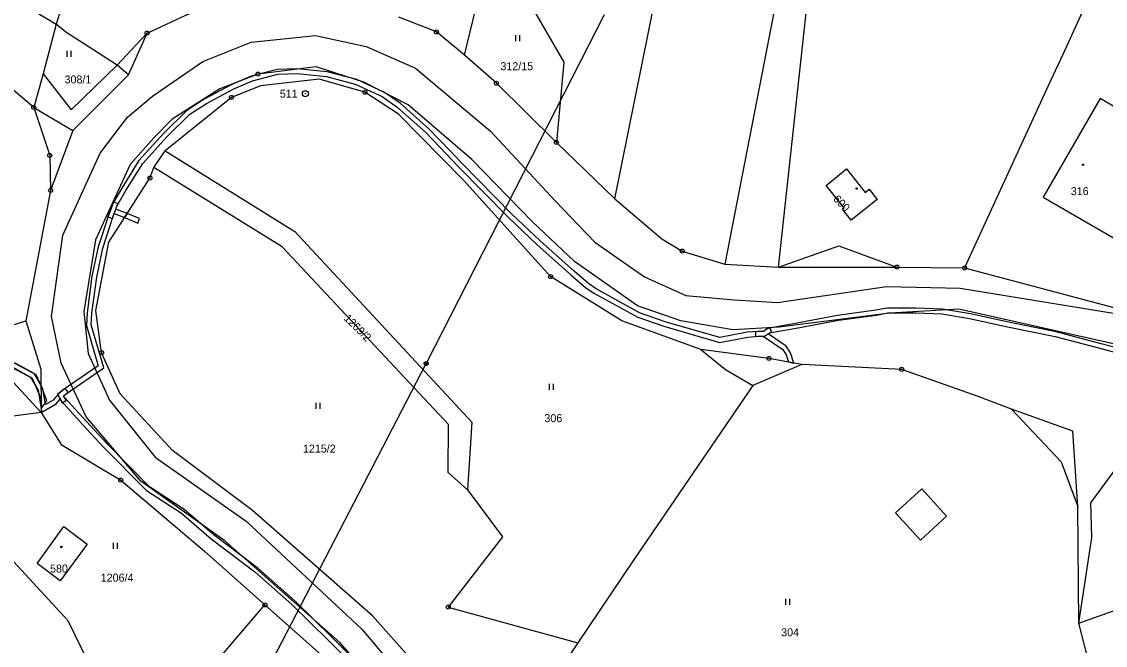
# Model space of a CAD drawing. Extents: x -745926 to -742978, y -968282 to -965689.
# Drawn here: x -745276.5 to -745141.1, y -967249.8 to -967171.8 of the extents above; entities that cross this region are included whole.
import ezdxf

# ---------------------------------------------------------------- set-up
doc = ezdxf.new("R2010")
doc.units = 0
for name, color, linetype in [('Hranice parcel', 7, 'Continuous'), ('Parcelní čísla', 7, 'Continuous'), ('Poz předměty', 7, 'Continuous'), ('Vnitřní kresba', 7, 'Continuous'), ('Věcná břemena k části', 7, 'Continuous'), ('Značky bodu BP', 7, 'Continuous'), ('Značky budov', 7, 'Continuous'), ('Značky kultur', 7, 'Continuous')]:
    doc.layers.add(name, color=color, linetype=linetype)

msp = doc.modelspace()

# ---------------------------------------------------------------- linework, layer by layer
at = {"layer": 'Hranice parcel'}
for p, q in [((-745202.34, -967193.92), (-745183.65, -967100.66)), ((-745221.16, -967175.97), (-745217.61, -967161.45)), ((-745275.54, -967170.09), (-745272.2, -967172.1)), ((-745270.1, -967185.4), (-745263.16, -967178.41)), ((-745275, -967182.5), (-745270.1, -967185.4)), ((-745209.67, -967186.88), (-745202.34, -967193.92)), ((-745259.97, -967189.99), (-745258.56, -967187.92)), ((-745274.07, -967220.66), (-745278.53, -967215.81)), ((-745223.18, -967244.98), (-745207, -967249.46)), ((-745144.35, -967246.97), (-745139.43, -967245.24)), ((-745141.85, -967256.86), (-745144.35, -967246.97)), ((-745207, -967249.46), (-745216.49, -967263.75))]:
    msp.add_line(p, q, dxfattribs=at)
for points in [[(-745168.16, -967104.13), (-745173.28, -967123.27), (-745188.63, -967202.08)], [(-745217.61, -967161.45), (-745208.73, -967176.85), (-745209.67, -967186.88)], [(-745275, -967182.5), (-745281.4, -967177.1), (-745298.48, -967162.66)], [(-745140.8, -967163.7), (-745146.38, -967175.86), (-745148.19, -967179.8), (-745158.64, -967202.56)], [(-745263.16, -967178.41), (-745260.83, -967173.2), (-745253.64, -967169.89), (-745250.27, -967169.74)], [(-745221.16, -967175.97), (-745224.66, -967173.06), (-745229.35, -967171.2)], [(-745272.2, -967172.1), (-745273.8, -967178.3), (-745275, -967182.5)], [(-745263.16, -967178.41), (-745264.55, -967177.2), (-745271, -967173.1), (-745272.2, -967172.1)], [(-745209.67, -967186.88), (-745217.17, -967179.47), (-745221.16, -967175.97)], [(-745178.97, -967214.64), (-745183.09, -967213.89), (-745191.6, -967212.75), (-745201.47, -967209.19), (-745210.38, -967203.66), (-745221.27, -967191.59), (-745229.41, -967183.34), (-745233.59, -967180.6), (-745239.31, -967178.98), (-745246.66, -967179.79), (-745250.28, -967181.24), (-745258.56, -967187.92)], [(-745136.34, -967182.81), (-745137.14, -967184.06), (-745141.69, -967181.37), (-745148.83, -967193.7), (-745135.5, -967201.42), (-745132.62, -967196.44), (-745133.07, -967196.18), (-745128.13, -967187.52)], [(-745329.38, -967185.24), (-745316.28, -967189.84), (-745298.54, -967197.66), (-745281.52, -967209.17), (-745278.48, -967209.96), (-745275.99, -967209.2)], [(-745270.1, -967185.4), (-745272.88, -967192.88), (-745273.88, -967198.16), (-745275.99, -967209.2)], [(-745258.56, -967187.92), (-745242.37, -967198.01), (-745220.24, -967221.85), (-745220.77, -967230.31)], [(-745216.49, -967263.75), (-745227.93, -967251.37), (-745232.64, -967246.06), (-745247.64, -967232.92), (-745257.66, -967225.39), (-745264.18, -967218.33), (-745266.51, -967213.17), (-745267.21, -967207.88), (-745265.62, -967199.33), (-745260.46, -967191.33), (-745259.97, -967189.99)], [(-745220.77, -967230.31), (-745223.2, -967228.15), (-745223.14, -967222.15), (-745243.93, -967199.91), (-745259.97, -967189.99)], [(-745169.56, -967194.02), (-745172.83, -967196.6), (-745173.9, -967195.22), (-745173.7, -967195.06), (-745175.96, -967192.25), (-745173.39, -967190.18), (-745171.07, -967193.15), (-745170.58, -967192.72), (-745169.56, -967194.02)], [(-745202.34, -967193.92), (-745196.49, -967198.94), (-745193.94, -967200.46), (-745188.63, -967202.08)], [(-745188.63, -967202.08), (-745181.92, -967202.47), (-745174.34, -967199.79), (-745167.09, -967202.46), (-745158.64, -967202.56)], [(-745158.64, -967202.56), (-745132.78, -967209.42), (-745128.69, -967209.96), (-745124.38, -967209.63), (-745120.27, -967208.73), (-745116.54, -967206.77), (-745113.27, -967203.97), (-745111.01, -967201.48)], [(-745275.99, -967209.2), (-745274.09, -967215.21), (-745274.07, -967220.66)], [(-745178.97, -967214.64), (-745185.11, -967217.25), (-745200.01, -967239.09), (-745207, -967249.46)], [(-745144.35, -967246.97), (-745144.47, -967232.42), (-745145.11, -967222.97), (-745152.79, -967220.23), (-745156.94, -967218.65), (-745166.5, -967215.25), (-745178.97, -967214.64)], [(-745274.07, -967220.66), (-745271.56, -967224.66), (-745264.12, -967229.1), (-745253.65, -967237.99), (-745246.09, -967244.71)], [(-745292.54, -967223.04), (-745270.72, -967246.67), (-745265.83, -967256.76)], [(-745220.77, -967230.31), (-745216.42, -967236.2), (-745223.18, -967244.98)], [(-745271.23, -967234.9), (-745268.3, -967237.1), (-745271.7, -967241.71), (-745274.57, -967239.54), (-745271.23, -967234.9)], [(-745261.92, -967263.24), (-745260.97, -967262.13), (-745246.09, -967244.71)], [(-745246.09, -967244.71), (-745234.23, -967255.25), (-745221.54, -967274.51)]]:
    msp.add_lwpolyline(points, dxfattribs=at)
at = {"layer": 'Poz předměty'}
for p in [(-745203.68, -967170.92), (-745248.43, -967257.95)]:
    msp.add_line(p, (-745225.94, -967214.52), dxfattribs=at)
for radius in [0.25, 0.2, 0.15, 0.1, 0.05]:
    msp.add_circle((-745225.94, -967214.52), radius, dxfattribs=at)
at = {"layer": 'Vnitřní kresba'}
for p, q in [((-745181.92, -967202.47), (-745173.28, -967123.27)), ((-745266.1, -967152.9), (-745272.2, -967172.1)), ((-745261.55, -967174), (-745260.83, -967173.2)), ((-745247.83, -967174.35), (-745239.76, -967173.5)), ((-745239.76, -967173.5), (-745233.44, -967174.87)), ((-745264.55, -967177.2), (-745261.55, -967174)), ((-745253.84, -967176.77), (-745247.83, -967174.35)), ((-745233.44, -967174.87), (-745227.28, -967177.58)), ((-745270.3, -967182.8), (-745264.55, -967177.2)), ((-745260.13, -967181.09), (-745253.84, -967176.77)), ((-745239.69, -967177.43), (-745246.97, -967178.33)), ((-745233.72, -967179.33), (-745239.69, -967177.43)), ((-745227.28, -967177.58), (-745217.92, -967185.47)), ((-745273.8, -967178.3), (-745270.3, -967182.8)), ((-745246.97, -967178.33), (-745251.73, -967180.19)), ((-745228.21, -967182.17), (-745233.72, -967179.33)), ((-745251.73, -967180.19), (-745257.67, -967183.97)), ((-745263.26, -967183.7), (-745260.13, -967181.09)), ((-745275, -967182.5), (-745273, -967188.5)), ((-745220.23, -967189.01), (-745228.21, -967182.17)), ((-745266.68, -967188.2), (-745263.26, -967183.7)), ((-745257.67, -967183.97), (-745259.98, -967186.31)), ((-745217.92, -967185.47), (-745209.81, -967194.16)), ((-745259.98, -967186.31), (-745262.92, -967189.65)), ((-745273, -967188.5), (-745272.88, -967192.88)), ((-745271.34, -967198.48), (-745266.68, -967188.2)), ((-745262.92, -967189.65), (-745267.29, -967199.06)), ((-745212.7, -967196.78), (-745220.23, -967189.01)), ((-745209.81, -967194.16), (-745204.85, -967199.36)), ((-745207.41, -967201.77), (-745212.7, -967196.78)), ((-745272.79, -967208.64), (-745271.34, -967198.48)), ((-745267.29, -967199.06), (-745268.74, -967208.02)), ((-745204.85, -967199.36), (-745198.64, -967203.69)), ((-745199.51, -967207.32), (-745207.41, -967201.77)), ((-745198.64, -967203.69), (-745193.49, -967206.02)), ((-745181.92, -967202.47), (-745167.09, -967202.46)), ((-745182.01, -967206.91), (-745168.41, -967204.9)), ((-745168.41, -967204.9), (-745159.2, -967205.09)), ((-745159.2, -967205.09), (-745132.78, -967209.42)), ((-745193.49, -967206.02), (-745187.43, -967206.57)), ((-745194.1, -967209.19), (-745199.51, -967207.32)), ((-745187.43, -967206.57), (-745182.01, -967206.91)), ((-745159.37, -967207.72), (-745167.98, -967208.21)), ((-745133.6, -967213.53), (-745159.37, -967207.72)), ((-745271.56, -967214.49), (-745272.79, -967208.64)), ((-745268.74, -967208.02), (-745268.19, -967213.26)), ((-745167.98, -967208.21), (-745181.8, -967209.97)), ((-745187.59, -967210.32), (-745194.1, -967209.19)), ((-745181.8, -967209.97), (-745187.59, -967210.32)), ((-745191.6, -967212.75), (-745188.51, -967215.27)), ((-745268.45, -967221.18), (-745271.56, -967214.49)), ((-745268.19, -967213.26), (-745265.52, -967219.12)), ((-745188.51, -967215.27), (-745185.11, -967217.25)), ((-745265.52, -967219.12), (-745259.8, -967226.22)), ((-745274.07, -967220.66), (-745292.54, -967223.04)), ((-745261.59, -967229.23), (-745268.45, -967221.18)), ((-745152.79, -967220.23), (-745146.59, -967226.8)), ((-745259.8, -967226.22), (-745248.44, -967234.23)), ((-745142.87, -967231.93), (-745138.92, -967226.57)), ((-745146.59, -967226.8), (-745144.47, -967232.42)), ((-745251.09, -967236.71), (-745261.59, -967229.23)), ((-745167.28, -967233.19), (-745164, -967230.19)), ((-745164, -967230.19), (-745160.9, -967233.6)), ((-745142.75, -967236.26), (-745142.87, -967231.93)), ((-745164.17, -967236.59), (-745167.28, -967233.19)), ((-745248.44, -967234.23), (-745233.99, -967247.73)), ((-745160.9, -967233.6), (-745164.17, -967236.59)), ((-745236.74, -967249.4), (-745251.09, -967236.71)), ((-745144.35, -967246.97), (-745142.75, -967236.26)), ((-745233.99, -967247.73), (-745229.89, -967252.56)), ((-745232.33, -967254.41), (-745236.74, -967249.4))]:
    msp.add_line(p, q, dxfattribs=at)
at = {"layer": 'Věcná břemena k části'}
for points in [[(-745137.88, -967213.02), (-745141.75, -967212), (-745147.19, -967210.55), (-745153.16, -967209.34), (-745157.92, -967208.3), (-745161.42, -967207.72), (-745164.73, -967207.6), (-745168.3, -967207.6), (-745169.75, -967207.87), (-745174.51, -967208.5), (-745179.34, -967209.43), (-745183.24, -967210.13), (-745183.83, -967210.5), (-745184.49, -967210.52), (-745185.82, -967210.61), (-745189.24, -967211.28), (-745196.06, -967209.29), (-745199.26, -967208.17), (-745204.68, -967205.2), (-745205.65, -967204.53), (-745207.45, -967202.99), (-745211.7, -967199.19), (-745215.24, -967195.84), (-745221.54, -967189.43), (-745222.9, -967187.96), (-745225.62, -967185.16), (-745229.17, -967181.97), (-745231.16, -967180.62), (-745234.62, -967179.01), (-745238.3, -967178.04), (-745242.06, -967177.66), (-745244.55, -967177.76), (-745247.83, -967178.61), (-745250.25, -967179.64), (-745253.68, -967181.47), (-745255.86, -967182.88), (-745258.75, -967185.72), (-745261.84, -967189.15), (-745264, -967192.6), (-745265.16, -967194.6), (-745265.37, -967195.28), (-745265.61, -967195.9), (-745266.95, -967199.95), (-745267.71, -967203.61)], [(-745233.98, -967252.49), (-745237.73, -967248.75), (-745242.32, -967244.23), (-745246.97, -967240.11), (-745252.43, -967236), (-745256.17, -967232.77), (-745260.52, -967229.92), (-745265.87, -967224.52), (-745268.41, -967221.77), (-745271.1, -967218.83), (-745271.26, -967218.55), (-745270.94, -967218.3), (-745266.25, -967215.07), (-745267.8, -967209.7), (-745267.71, -967208.24), (-745267.11, -967203.71), (-745266.37, -967200.11), (-745265.05, -967196.1), (-745264.81, -967195.48), (-745264.6, -967194.84), (-745263.48, -967192.9), (-745261.36, -967189.51), (-745258.31, -967186.14), (-745255.48, -967183.36), (-745253.38, -967181.99), (-745249.99, -967180.18), (-745247.63, -967179.17), (-745244.47, -967178.36), (-745242.08, -967178.26), (-745238.4, -967178.64), (-745234.82, -967179.57), (-745231.46, -967181.14), (-745229.55, -967182.45), (-745226.04, -967185.6), (-745223.34, -967188.38), (-745221.98, -967189.85), (-745215.66, -967196.26), (-745212.1, -967199.63), (-745207.85, -967203.45), (-745206.01, -967205.01), (-745205, -967205.72), (-745199.5, -967208.71), (-745196.24, -967209.87), (-745189.26, -967211.9), (-745185.74, -967211.21), (-745184.47, -967211.12), (-745183.65, -967211.1), (-745183.02, -967210.69), (-745179.24, -967210.03), (-745174.41, -967209.1), (-745169.65, -967208.47), (-745168.24, -967208.2), (-745164.75, -967208.2), (-745161.48, -967208.32), (-745158.04, -967208.88), (-745153.28, -967209.92), (-745147.33, -967211.13), (-745141.91, -967212.58), (-745138.02, -967213.6)], [(-745267.71, -967203.61), (-745268.31, -967208.18), (-745268.4, -967209.76), (-745266.95, -967214.83), (-745271.3, -967217.82), (-745272.04, -967218.41), (-745271.58, -967219.19), (-745268.85, -967222.17), (-745266.31, -967224.94), (-745260.9, -967230.38), (-745256.53, -967233.25), (-745252.81, -967236.46), (-745247.35, -967240.57), (-745242.72, -967244.67), (-745238.15, -967249.17), (-745234.64, -967252.69), (-745234.83, -967253.58), (-745235.28, -967253.88), (-745234.94, -967254.38), (-745234.29, -967253.94), (-745233.98, -967252.49)], [(-745282.97, -967212.21), (-745275.17, -967216.35), (-745274.08, -967218.99), (-745274.07, -967220.17), (-745273.37, -967219.14), (-745274.08, -967217.3), (-745274.69, -967215.93), (-745282.67, -967211.69)], [(-745277.6, -967214.99), (-745275.38, -967216.21), (-745274.45, -967217.86), (-745274.07, -967220.17), (-745274, -967220.61), (-745272.19, -967219.56), (-745271.7, -967218.99), (-745271.45, -967219.42), (-745270.93, -967219.12), (-745271.26, -967218.55), (-745270.7, -967218.11), (-745271.07, -967217.64), (-745271.86, -967218.26), (-745272.57, -967219.1), (-745273.54, -967219.65), (-745273.87, -967217.68), (-745274.08, -967217.3), (-745274.94, -967215.77), (-745277.32, -967214.47)]]:
    msp.add_lwpolyline(points, dxfattribs=at)
for points in [[(-745265.72, -967196.17), (-745265.16, -967196.39), (-745264.92, -967195.77), (-745263.66, -967196.28), (-745263.33, -967195.77), (-745264.72, -967195.21), (-745264.5, -967194.53), (-745265.07, -967194.34), (-745265.37, -967195.28)], [(-745263.33, -967195.77), (-745263.66, -967196.28), (-745261.99, -967196.96), (-745261.77, -967196.4)], [(-745180.93, -967212.35), (-745183.19, -967210.82), (-745182.72, -967210.51), (-745183.04, -967210.01), (-745183.83, -967210.5), (-745184.79, -967210.54), (-745184.77, -967211.14), (-745183.83, -967211.11), (-745181.37, -967212.77), (-745180.95, -967213.45), (-745180.65, -967214.33), (-745179.97, -967214.46), (-745180.41, -967213.19)]]:
    msp.add_lwpolyline(points, close=True, dxfattribs=at)
at = {"layer": 'Značky bodu BP'}
for centre, radius in [((-745260.83, -967173.2), 0.25), ((-745260.83, -967173.2), 0.0152), ((-745224.66, -967173.06), 0.25), ((-745224.66, -967173.06), 0.0152), ((-745246.97, -967178.33), 0.25), ((-745246.97, -967178.33), 0.0152), ((-745217.17, -967179.47), 0.25), ((-745241.04, -967180.78), 0.375), ((-745233.59, -967180.6), 0.25), ((-745233.59, -967180.6), 0.0152), ((-745217.17, -967179.47), 0.0152), ((-745250.28, -967181.24), 0.25), ((-745250.28, -967181.24), 0.0152), ((-745241.04, -967180.78), 0.015), ((-745275, -967182.5), 0.25), ((-745275, -967182.5), 0.0152), ((-745209.67, -967186.88), 0.25), ((-745209.67, -967186.88), 0.0152), ((-745273, -967188.5), 0.25), ((-745273, -967188.5), 0.0152), ((-745260.46, -967191.33), 0.25), ((-745260.46, -967191.33), 0.0152), ((-745272.88, -967192.88), 0.25), ((-745272.88, -967192.88), 0.0152), ((-745193.94, -967200.46), 0.25), ((-745193.94, -967200.46), 0.0152), ((-745167.09, -967202.46), 0.25), ((-745158.64, -967202.56), 0.25), ((-745210.38, -967203.66), 0.25), ((-745210.38, -967203.66), 0.0152), ((-745167.09, -967202.46), 0.0152), ((-745158.64, -967202.56), 0.0152), ((-745266.51, -967213.17), 0.25), ((-745266.51, -967213.17), 0.0152), ((-745183.09, -967213.89), 0.25), ((-745183.09, -967213.89), 0.0152), ((-745166.5, -967215.25), 0.25), ((-745166.5, -967215.25), 0.0152), ((-745264.12, -967229.1), 0.25), ((-745264.12, -967229.1), 0.0152), ((-745246.09, -967244.71), 0.25), ((-745246.09, -967244.71), 0.0152), ((-745223.18, -967244.98), 0.25), ((-745223.18, -967244.98), 0.0152)]:
    msp.add_circle(centre, radius, dxfattribs=at)
at = {"layer": 'Značky budov'}
for centre in [(-745143.83, -967189.67), (-745172.15, -967192.65), (-745271.53, -967237.46)]:
    msp.add_circle(centre, 0.0875, dxfattribs=at)
at = {"layer": 'Značky kultur'}
for p, q in [((-745214.75, -967174.23), (-745214.75, -967173.48)), ((-745214.24, -967174.23), (-745214.24, -967173.48)), ((-745270.81, -967176.18), (-745270.81, -967175.43)), ((-745270.31, -967176.18), (-745270.31, -967175.43)), ((-745210.54, -967217.82), (-745210.54, -967217.07)), ((-745210.04, -967217.82), (-745210.04, -967217.07)), ((-745239.68, -967220.18), (-745239.68, -967219.43)), ((-745239.18, -967220.18), (-745239.18, -967219.43)), ((-745265.02, -967237.7), (-745265.02, -967236.95)), ((-745264.52, -967237.7), (-745264.52, -967236.95)), ((-745181, -967244.68), (-745181, -967243.93)), ((-745180.49, -967244.68), (-745180.49, -967243.93))]:
    msp.add_line(p, q, dxfattribs=at)

# ---------------------------------------------------------------- texts
at = {"layer": 'Parcelní čísla'}
for s, p in [('312/15', (-745216.66, -967177.84)), ('308/1', (-745271.14, -967179.5)), ('316', (-745145.37, -967193.47)), ('306', (-745211.16, -967221.85)), ('1215/2', (-745241.34, -967225.66)), ('580', (-745272.95, -967240.66)), ('1206/4', (-745266.62, -967241.8)), ('304', (-745181.57, -967248.63))]:
    msp.add_text(s, height=1, dxfattribs=at).set_placement(p)
for s, p in [('600', (-745175.15, -967194.04)), ('1269/2', (-745236.3, -967208.96))]:
    msp.add_text(s, height=1, rotation=315, dxfattribs=at).set_placement(p)
at = {"layer": 'Značky bodu BP'}
msp.add_text('511', height=1, dxfattribs=at).set_placement((-745244.24, -967181.28))

doc.saveas('drawing.dxf')
